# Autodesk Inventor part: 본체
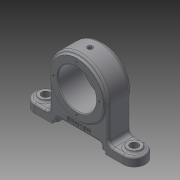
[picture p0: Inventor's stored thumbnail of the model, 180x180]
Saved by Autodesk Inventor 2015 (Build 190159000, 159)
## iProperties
Created: 2019-05
Part Number: 본체
Material: 일반
Document SubType Name: Modeling
Designer: 102101
Density: 1 g/cm^3
Appearance: 기본값
Author: 102101
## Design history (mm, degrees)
sketch "스케치1"
  geometry: L1 (75, -15)-(-75, -15); L2 (-75, -15)-(-75, 15); L3 (-75, 15)-(75, 15); L4 (75, 15)-(75, -15); L5 (75, -15)-(-75, 15); L6 (-75, -15)-(75, 15); 1 further point
  constraints: 12 end point, 2 midpoint, 2 parallel, 1 horizontal, 1 perpendicular
  dimensions: "d0" = 150 distance of L2.end L3.end; "d1" = 30 distance of L3.end L1.start
extrude "돌출1" new body sketch "스케치1" distance "d2" = 12; taper "d3" = 0 deg
fillet "모깎기1" dims "d4" = 15
fillet "모깎기2" dims "d5" = 15
sketch "스케치2"
  geometry: C1 r 9 at (-60, 0); C2 r 9 at (60, 0); 1 further point
  constraints: 2 centre point, 2 horizontal alignment
  dimensions: "d6" = 18 diameter of C1; "d7" = 18 diameter of C2; "d8" = 120 distance of C2.centre C1.centre; "d9" = 60 distance of point (0, 0) C1.centre
extrude "돌출2" join sketch "스케치2" distance "d10" = 3; taper "d11" = 0 deg
sketch "스케치3"
  geometry: L1 (0, 0)-(-120, 0) reference; L2 (-96, 0)-(-24, 0); L3 (-24, 0)-(-24, 4); L4 (-24, 4)-(-96, 4); L5 (-96, 4)-(-96, 0); 2 further points
  constraints: 8 end point, 2 midpoint, 2 parallel, 1 horizontal, 1 perpendicular, 1 point on line
  dimensions: "d12" = 72 distance of L3.end L4.end; "d13" = 4 distance between parallel lines of L4 L1
extrude "돌출3" cut sketch "스케치3" stored distance "d14" = 3; taper "d15" = 0 deg
sketch "스케치4"
  geometry: L1 (-96, 4)-(-24, 4) reference; L2 (-90, 4)-(-30, 4); L3 (-30, 4)-(-30, 10); L4 (-30, 10)-(-90, 10); L5 (-90, 10)-(-90, 4); 2 further points
  constraints: 8 end point, 2 midpoint, 2 parallel, 1 horizontal, 1 perpendicular, 1 point on line
  dimensions: "d16" = 60 distance between parallel lines of L3 L5; "d17" = 6 distance between parallel lines of L1 L4
extrude "돌출4" cut sketch "스케치4" stored distance "d18" = 3; taper "d19" = 0 deg
sketch "스케치5"
  geometry: L1 (40, -15)-(-40, -15); L2 (-40, -15)-(-40, 15); L3 (-40, 15)-(40, 15); L4 (40, 15)-(40, -15); L5 (40, -15)-(-40, 15); L6 (-40, -15)-(40, 15); 1 further point
  constraints: 12 end point, 2 midpoint, 2 parallel, 1 horizontal, 1 perpendicular
  dimensions: "d20" = 80 distance of L2.end L3.end; "d21" = 30 distance between parallel lines of L1 L3
extrude "돌출5" join sketch "스케치5" distance "d22" = 48; taper "d23" = 0 deg
sketch "스케치6"
  geometry: L1 (40, 60)-(-40, 60) reference; L2 (-36, 4)-(-36, 0) reference; L3 (-36, 0)-(-75, 0) reference; L4 (-75, 0)-(-75, 12) reference; L5 (-75, 12)-(-69, 12) reference; L6 (-69, 12)-(-69, 15) reference; L7 (-69, 15)-(-51, 15) reference; L8 (-51, 15)-(-51, 12) reference; L9 (-51, 12)-(-40, 12) reference; L10 (-40, 12)-(-40, 60) reference; L11 (-40, 60)-(40, 60) reference; L12 (40, 60)-(40, 12) reference; L13 (40, 12)-(51, 12) reference; L14 (51, 12)-(51, 15) reference; L15 (51, 15)-(69, 15) reference; L16 (69, 15)-(69, 12) reference; L17 (69, 12)-(75, 12) reference; L18 (75, 12)-(75, 0) reference; L19 (75, 0)-(36, 0) reference; L20 (36, 0)-(36, 4) reference; L21 (36, 4)-(30, 4) reference; L22 (30, 4)-(30, 10) reference; L23 (30, 10)-(-30, 10) reference; L24 (-30, 10)-(-30, 4) reference; L25 (-30, 4)-(-36, 4) reference; C1 r 40 at (0, 60); 3 further points
  constraints: 3 vertical alignment, 2 midpoint, 1 centre point
  dimensions: "d24" = 80 diameter of C1; "d25" = 60 distance of point (0, 0) C1.centre
extrude "돌출6" join sketch "스케치6" stored distance "d26" = 30; taper "d27" = 0 deg
sketch "스케치7"
  geometry: L1 (-36, 4)-(-36, 0) reference; L2 (-36, 0)-(-75, 0) reference; L3 (-75, 0)-(-75, 12) reference; L4 (-75, 12)-(-69, 12) reference; L5 (-69, 12)-(-69, 15) reference; L6 (-69, 15)-(-51, 15) reference; L7 (-51, 15)-(-51, 12) reference; L8 (-51, 12)-(-40, 12) reference; L9 (-40, 12)-(-40, 60) reference; L10 (40, 60)-(40, 12) reference; L11 (40, 12)-(51, 12) reference; L12 (51, 12)-(51, 15) reference; L13 (51, 15)-(69, 15) reference; L14 (69, 15)-(69, 12) reference; L15 (69, 12)-(75, 12) reference; L16 (75, 12)-(75, 0) reference; L17 (75, 0)-(36, 0) reference; L18 (36, 0)-(36, 4) reference; L19 (36, 4)-(30, 4) reference; L20 (30, 4)-(30, 10) reference; L21 (30, 10)-(-30, 10) reference; L22 (-30, 10)-(-30, 4) reference; L23 (-30, 4)-(-36, 4) reference; C1 r 36 at (0, 60); A1 r 40 centre (0, 60) between (40, 60) and (-40, 60) reference; 1 further point
  constraints: 1 centre point, 1 coincident
  dimensions: "d28" = 72 diameter of C1
extrude "돌출7" join sketch "스케치7" stored distance "d29" = 36; taper "d30" = 0 deg
sketch "스케치8"
  geometry: C1 r 26 at (0, 0); 1 further point
  constraints: 1 centre point, 1 vertical alignment
  dimensions: "d31" = 52 diameter of C1; "d32" = 60 distance of point (0, -60) C1.centre
extrude "돌출8" cut sketch "스케치8" stored distance "d33" = 10; taper "d34" = 0 deg
sketch "스케치9"
  geometry: 2 further points
  dimensions: "d35" = 91 distance of point (0, -60) point (0, 31)
hole "구멍1" sketch "스케치9" at (0, 31) diameter "d36" = 3.242; stored, may be unused: countersink angle "d40" = 90 deg, drill point angle "d42" = 118 deg; dims "d37" = 6, "d38" = 4, "d39" = 2, "d41" = 8
sketch "스케치10"
  geometry: A1 r 15 centre (0, 0) between (0, 15) and (0, -15) reference; 1 further point
hole "구멍2" sketch "스케치10" at (0, 0) diameter "d46" = 11; stored, may be unused: countersink angle "d50" = 90 deg, drill point angle "d52" = 118 deg; dims "d47" = 6, "d48" = 4, "d49" = 2, "d51" = 8
node "작업 평면1"
sketch "스케치11"
  geometry: 1 further point
hole "구멍3" sketch "스케치11" at (0, 0) diameter "d54" = 4.917; stored, may be unused: countersink angle "d58" = 90 deg, drill point angle "d60" = 118 deg; dims "d55" = 8, "d56" = 7, "d57" = 1, "d59" = 10
sketch "스케치12"
  geometry: 1 further point
hole "구멍4" sketch "스케치12" at (0, 0) diameter "d61" = 2; stored, may be unused: countersink angle "d65" = 90 deg, drill point angle "d67" = 118 deg; dims "d62" = 8, "d63" = 7, "d64" = 1, "d66" = 30
fillet "모깎기3" dims "d68" = 3
chamfer "모따기1" distance "d69" = 1; stored, may be unused: second distance "d70" = 2, angle "d71" = 45 deg
sketch "스케치13"
  geometry: C1 r 1.5 at (0, 26); 2 further points
  constraints: 2 vertical alignment, 1 centre point, 1 other
  dimensions: "d72" = 3 diameter of C1
extrude "돌출9" cut sketch "스케치13" stored distance "d73" = 10; taper "d74" = 0 deg
fillet "모깎기4" dims "d75" = 6
fillet "모깎기5" dims "d76" = 3
fillet "모깎기6" dims "d77" = 3
fillet "모깎기7" dims "d78" = 3
fillet "모깎기8" dims "d79" = 3
sketch "스케치14"
  geometry: L1 (-63, 10)-(-9, 10) reference; 2 further points
  constraints: 1 vertical alignment, 1 other
  dimensions: "d80" = 7 distance from line of L1 point (-36, 17)
feature "엠보싱1" sketch "스케치14" dims "d0" = 150, "d1" = 30, "d81" = 0.5, "d82" = 0
node "솔리드1"
pattern_circular "원형 패턴1" dims angle "d44" = 360 deg
mirror "대칭1"
mirror "대칭2"
node "절단 모서리 투영1"
node "절단 모서리 투영2"
